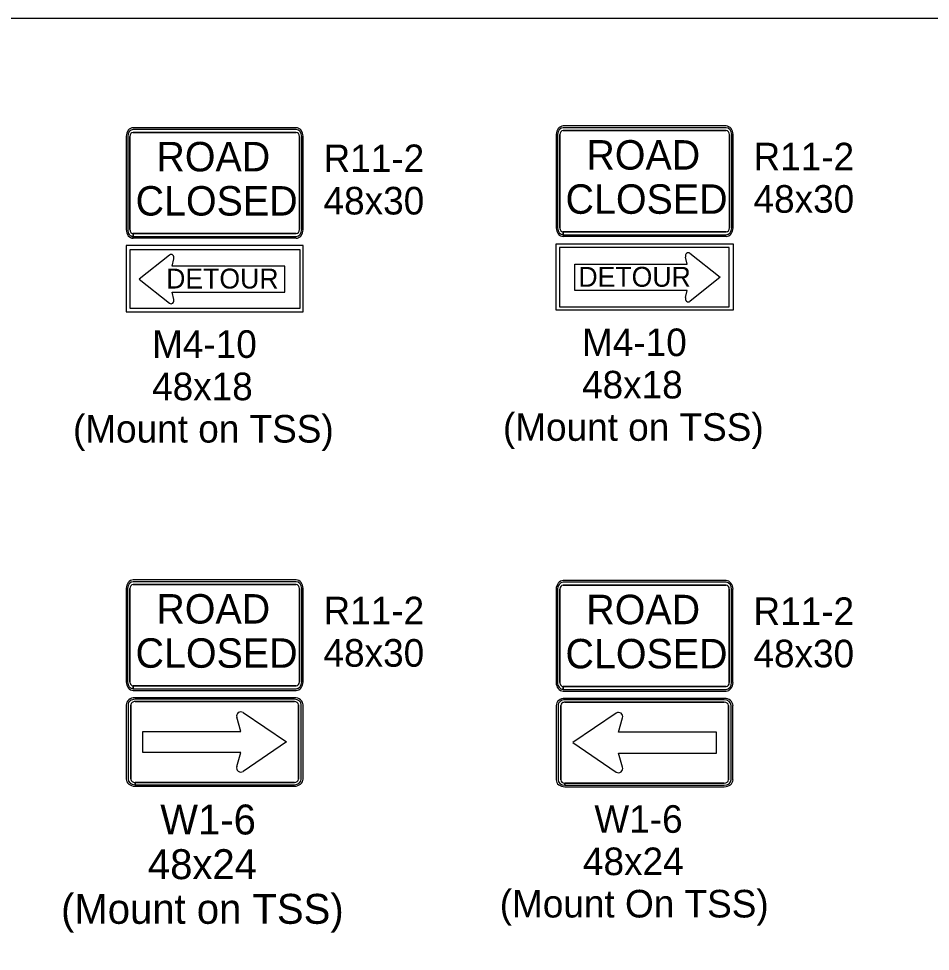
# Model space of a CAD drawing. Extents: x 1458 to 4498, y 17709 to 24109.
# Drawn here: x 3157 to 3652, y 21403 to 21909 of the extents above; entities that cross this region are included whole.
import ezdxf

# ---------------------------------------------------------------- set-up
doc = ezdxf.new("R2010")
doc.units = 0
doc.layers.add('P_TRAF_TCP_General', color=7, linetype='Continuous')

msp = doc.modelspace()

# ---------------------------------------------------------------- linework, layer by layer
at = {"layer": 'P_TRAF_TCP_General'}
for p, q in [((3307.71, 21849.89), (3219.25, 21849.89)), ((3307.71, 21848.95), (3219.25, 21848.95)), ((3307.71, 21848.95), (3219.25, 21848.95)), ((3307.71, 21847.39), (3219.25, 21847.39)), ((3219.25, 21847.39), (3307.71, 21847.39)), ((3541.06, 21850.85), (3452.59, 21850.85)), ((3541.06, 21849.91), (3452.59, 21849.91)), ((3541.06, 21849.91), (3452.59, 21849.91)), ((3541.06, 21848.35), (3452.59, 21848.35)), ((3452.59, 21848.35), (3541.06, 21848.35)), ((3215.5, 21845.2), (3215.5, 21794.6)), ((3216.25, 21845.2), (3216.25, 21794.6)), ((3216.25, 21845.2), (3216.25, 21794.6)), ((3217.5, 21845.2), (3217.5, 21794.6)), ((3217.5, 21794.6), (3217.5, 21845.2)), ((3309.46, 21794.6), (3309.46, 21845.2)), ((3309.46, 21845.2), (3309.46, 21794.6)), ((3310.71, 21794.6), (3310.71, 21845.2)), ((3310.71, 21794.6), (3310.71, 21845.2)), ((3311.46, 21794.6), (3311.46, 21845.2)), ((3448.85, 21846.16), (3448.85, 21795.56)), ((3449.6, 21846.16), (3449.6, 21795.56)), ((3449.6, 21846.16), (3449.6, 21795.56)), ((3450.84, 21846.16), (3450.84, 21795.56)), ((3450.84, 21795.56), (3450.84, 21846.16)), ((3542.81, 21795.56), (3542.81, 21846.16)), ((3542.81, 21846.16), (3542.81, 21795.56)), ((3544.06, 21795.56), (3544.06, 21846.16)), ((3544.06, 21795.56), (3544.06, 21846.16)), ((3544.81, 21795.56), (3544.81, 21846.16)), ((3219.25, 21792.41), (3307.71, 21792.41)), ((3219.25, 21790.85), (3219.25, 21792.41)), ((3307.71, 21792.41), (3219.26, 21792.41)), ((3219.26, 21792.41), (3219.26, 21790.85)), ((3452.59, 21793.37), (3541.06, 21793.37)), ((3452.59, 21791.81), (3452.59, 21793.37)), ((3452.59, 21791.81), (3541.06, 21791.81)), ((3541.06, 21793.37), (3452.61, 21793.37)), ((3452.61, 21793.37), (3452.61, 21791.81)), ((3452.61, 21791.81), (3541.06, 21791.81)), ((3307.71, 21789.91), (3218.91, 21789.91)), ((3219.25, 21790.85), (3307.71, 21790.85)), ((3219.26, 21790.85), (3307.71, 21790.85)), ((3541.06, 21790.87), (3452.25, 21790.87)), ((3521.39, 21781.76), (3537.81, 21768.69)), ((3238.93, 21780.8), (3222.51, 21767.74)), ((3240.37, 21774.81), (3241.34, 21778.73)), ((3519.96, 21775.77), (3518.99, 21779.69)), ((3301.48, 21774.81), (3240.37, 21774.81)), ((3301.48, 21760.67), (3301.48, 21774.81)), ((3458.84, 21775.77), (3519.96, 21775.77)), ((3458.84, 21761.62), (3458.84, 21775.77)), ((3222.51, 21767.74), (3238.92, 21754.68)), ((3537.81, 21768.69), (3521.4, 21755.64)), ((3519.96, 21761.62), (3458.84, 21761.62)), ((3518.98, 21757.68), (3519.96, 21761.62)), ((3241.34, 21756.72), (3240.37, 21760.67)), ((3240.37, 21760.67), (3301.48, 21760.67)), ((3307.69, 21604.36), (3219.23, 21604.36)), ((3215.48, 21599.67), (3215.48, 21549.07)), ((3216.23, 21599.67), (3216.23, 21549.07)), ((3216.23, 21599.67), (3216.23, 21549.07)), ((3217.48, 21599.67), (3217.48, 21549.07)), ((3217.48, 21549.07), (3217.48, 21599.67)), ((3307.69, 21603.42), (3219.23, 21603.42)), ((3307.69, 21603.42), (3219.23, 21603.42)), ((3307.69, 21601.86), (3219.23, 21601.86)), ((3219.23, 21601.86), (3307.69, 21601.86)), ((3309.44, 21549.07), (3309.44, 21599.67)), ((3309.44, 21599.67), (3309.44, 21549.07)), ((3310.69, 21549.07), (3310.69, 21599.67)), ((3310.69, 21549.07), (3310.69, 21599.67)), ((3311.44, 21549.07), (3311.44, 21599.67)), ((3448.8, 21599.33), (3448.8, 21548.72)), ((3449.55, 21599.33), (3449.55, 21548.72)), ((3449.55, 21599.33), (3449.55, 21548.72)), ((3450.8, 21599.33), (3450.8, 21548.72)), ((3450.8, 21548.72), (3450.8, 21599.33)), ((3541.02, 21604.01), (3452.55, 21604.01)), ((3541.02, 21603.08), (3452.55, 21603.08)), ((3541.02, 21603.08), (3452.55, 21603.08)), ((3541.02, 21601.51), (3452.55, 21601.51)), ((3452.55, 21601.51), (3541.02, 21601.51)), ((3542.76, 21548.72), (3542.76, 21599.33)), ((3542.76, 21599.33), (3542.76, 21548.72)), ((3544.01, 21548.72), (3544.01, 21599.33)), ((3544.01, 21548.72), (3544.01, 21599.33)), ((3544.76, 21548.72), (3544.76, 21599.33)), ((3219.23, 21546.88), (3307.69, 21546.88)), ((3219.23, 21545.32), (3219.23, 21546.88)), ((3219.23, 21545.32), (3307.69, 21545.32)), ((3219.23, 21544.38), (3307.69, 21544.38)), ((3307.69, 21546.88), (3219.24, 21546.88)), ((3219.24, 21546.88), (3219.24, 21545.32)), ((3219.24, 21545.32), (3307.69, 21545.32)), ((3452.55, 21546.54), (3541.02, 21546.54)), ((3452.55, 21544.97), (3452.55, 21546.54)), ((3452.55, 21544.97), (3541.02, 21544.97)), ((3452.55, 21544.04), (3541.01, 21544.04)), ((3541.02, 21546.54), (3452.56, 21546.54)), ((3452.56, 21546.54), (3452.56, 21544.97)), ((3452.56, 21544.97), (3541.02, 21544.97)), ((3306.7, 21540.38), (3220.23, 21540.38)), ((3306.7, 21539.58), (3220.23, 21539.58)), ((3540.02, 21540.04), (3453.55, 21540.04)), ((3540.02, 21539.24), (3453.55, 21539.24)), ((3215.48, 21536.59), (3215.48, 21496.2)), ((3216.48, 21536.59), (3216.48, 21496.2)), ((3217.98, 21536.59), (3217.98, 21496.2)), ((3217.98, 21496.2), (3217.98, 21536.59)), ((3306.7, 21538.38), (3220.23, 21538.38)), ((3220.23, 21538.38), (3306.7, 21538.38)), ((3308.94, 21496.2), (3308.94, 21536.59)), ((3308.94, 21536.59), (3308.94, 21496.2)), ((3310.44, 21496.2), (3310.44, 21536.59)), ((3311.44, 21496.2), (3311.44, 21536.59)), ((3448.8, 21536.24), (3448.8, 21495.86)), ((3449.8, 21536.24), (3449.8, 21495.86)), ((3451.3, 21536.24), (3451.3, 21495.86)), ((3451.3, 21495.86), (3451.3, 21536.24)), ((3540.02, 21538.04), (3453.55, 21538.04)), ((3453.55, 21538.04), (3540.02, 21538.04)), ((3542.27, 21495.86), (3542.27, 21536.24)), ((3542.27, 21536.24), (3542.27, 21495.86)), ((3543.77, 21495.86), (3543.77, 21536.24)), ((3544.76, 21495.86), (3544.76, 21536.24)), ((3277.67, 21522.07), (3275.42, 21529.84)), ((3278.89, 21532.36), (3302.46, 21516.39)), ((3481.37, 21532.02), (3457.8, 21516.05)), ((3482.58, 21521.72), (3484.84, 21529.49)), ((3224.48, 21522.07), (3277.67, 21522.07)), ((3224.48, 21510.72), (3224.48, 21522.07)), ((3535.78, 21521.72), (3482.58, 21521.72)), ((3535.78, 21510.38), (3535.78, 21521.72)), ((3302.46, 21516.39), (3278.86, 21500.41)), ((3457.8, 21516.05), (3481.39, 21500.07)), ((3277.67, 21510.72), (3224.48, 21510.72)), ((3275.43, 21503), (3277.67, 21510.72)), ((3484.82, 21502.65), (3482.58, 21510.38)), ((3482.58, 21510.38), (3535.78, 21510.38)), ((3220.23, 21494.4), (3306.7, 21494.4)), ((3220.23, 21493.2), (3220.23, 21494.4)), ((3306.7, 21494.4), (3220.25, 21494.4)), ((3220.25, 21494.4), (3220.25, 21493.2)), ((3220.25, 21493.2), (3306.7, 21493.2)), ((3453.55, 21494.06), (3540.02, 21494.06)), ((3453.55, 21492.86), (3453.55, 21494.06)), ((3540.02, 21494.06), (3453.57, 21494.06)), ((3453.57, 21494.06), (3453.57, 21492.86)), ((3220.23, 21492.4), (3306.7, 21492.4)), ((3453.55, 21492.06), (3540.02, 21492.06)), ((3453.57, 21492.86), (3540.02, 21492.86))]:
    msp.add_line(p, q, dxfattribs=at)
for points in [[(4498.44, 21909.14), (1458.44, 21909.14), (1458.44, 19909.14), (4498.44, 19909.14)], [(3448.85, 21786.87), (3544.81, 21786.87), (3544.81, 21750.89), (3448.85, 21750.89)], [(3311.48, 21785.92), (3215.51, 21785.92), (3215.51, 21749.93), (3311.48, 21749.93)], [(3309.64, 21751.74), (3217.61, 21751.74), (3217.61, 21783.85), (3309.64, 21783.85)], [(3450.68, 21752.69), (3542.71, 21752.69), (3542.71, 21784.8), (3450.68, 21784.8)]]:
    msp.add_lwpolyline(points, close=True, dxfattribs=at)
for centre, start, end in [((3277.61, 21530.47), 55.884, 196.1777), ((3482.65, 21530.13), 343.8223, 124.116), ((3277.61, 21502.31), 162.5706, 303.37), ((3482.65, 21501.97), 236.63, 17.4294)]:
    msp.add_arc(centre, 2.28, start, end, dxfattribs=at)
for centre, major_axis, ratio, start_param, end_param in [((3219.25, 21845.2), (0, 4.69), 0.8, 0, 1.570796), ((3219.25, 21845.2), (0, 3.75), 0.8, 0, 1.570796), ((3219.25, 21845.2), (0, 3.75), 0.8, 0, 1.570796), ((3219.25, 21845.2), (0, 2.19), 0.8, 0, 1.570796), ((3219.25, 21845.2), (0, 2.19), 0.8, 0, 1.570796), ((3307.71, 21845.2), (0, 4.69), 0.8, 4.712389, 6.283185), ((3307.71, 21845.2), (0, 3.75), 0.8, 4.712389, 6.283185), ((3307.71, 21845.2), (0, 3.75), 0.8, 4.712389, 6.283185), ((3307.71, 21845.2), (0, 2.19), 0.8, 4.712389, 6.283185), ((3307.71, 21845.2), (0, 2.19), 0.8, 4.712389, 6.283185), ((3452.59, 21846.16), (0, 4.69), 0.8, 0, 1.570796), ((3452.59, 21846.16), (0, 3.75), 0.8, 0, 1.570796), ((3452.59, 21846.16), (0, 3.75), 0.8, 0, 1.570796), ((3452.59, 21846.16), (0, 2.19), 0.8, 0, 1.570796), ((3452.59, 21846.16), (0, 2.19), 0.8, 0, 1.570796), ((3541.06, 21846.16), (0, 4.69), 0.8, 4.712389, 6.283185), ((3541.06, 21846.16), (0, 3.75), 0.8, 4.712389, 6.283185), ((3541.06, 21846.16), (0, 3.75), 0.8, 4.712389, 6.283185), ((3541.06, 21846.16), (0, 2.19), 0.8, 4.712389, 6.283185), ((3541.06, 21846.16), (0, 2.19), 0.8, 4.712389, 6.283185), ((3219.25, 21794.6), (0, 4.69), 0.8, 1.570796, 3.141593), ((3219.25, 21794.6), (0, 3.75), 0.8, 1.570796, 3.141593), ((3219.25, 21794.6), (0, 3.75), 0.8, 1.570796, 3.141593), ((3219.25, 21794.6), (0, 2.19), 0.8, 1.570796, 3.141593), ((3219.25, 21794.6), (0, 2.19), 0.8, 1.570796, 3.141593), ((3307.71, 21794.6), (0, 3.75), 0.8, 3.141593, 4.712389), ((3307.71, 21794.6), (0, 2.19), 0.8, 3.141593, 4.712389), ((3307.71, 21794.6), (0, 3.75), 0.8, 3.141593, 4.712389), ((3307.71, 21794.6), (0, 2.19), 0.8, 3.141593, 4.712389), ((3307.71, 21794.6), (0, 4.69), 0.8, 3.141593, 4.712389), ((3452.59, 21795.56), (0, 4.69), 0.8, 1.570796, 3.141593), ((3452.59, 21795.56), (0, 3.75), 0.8, 1.570796, 3.141593), ((3452.59, 21795.56), (0, 3.75), 0.8, 1.570796, 3.141593), ((3452.59, 21795.56), (0, 2.19), 0.8, 1.570796, 3.141593), ((3452.59, 21795.56), (0, 2.19), 0.8, 1.570796, 3.141593), ((3541.06, 21795.56), (0, 3.75), 0.8, 3.141593, 4.712389), ((3541.06, 21795.56), (0, 2.19), 0.8, 3.141593, 4.712389), ((3541.06, 21795.56), (0, 3.75), 0.8, 3.141593, 4.712389), ((3541.06, 21795.56), (0, 2.19), 0.8, 3.141593, 4.712389), ((3541.06, 21795.56), (0, 4.69), 0.8, 3.141593, 4.712389), ((3520.51, 21780.21), (0, 1.86), 0.851337, 5.694845, 8.136509), ((3239.81, 21779.25), (0, 1.86), 0.851337, 4.429862, 6.871525), ((3239.81, 21756.22), (0, -1.86), 0.851337, 5.687791, 8.124104), ((3520.51, 21757.18), (0, -1.86), 0.851337, 4.442267, 6.878579), ((3219.23, 21599.67), (0, 4.69), 0.8, 0, 1.570796), ((3307.69, 21599.67), (0, 4.69), 0.8, 4.712389, 6.283185), ((3219.23, 21599.67), (0, 3.75), 0.8, 0, 1.570796), ((3219.23, 21599.67), (0, 3.75), 0.8, 0, 1.570796), ((3219.23, 21599.67), (0, 2.19), 0.8, 0, 1.570796), ((3219.23, 21599.67), (0, 2.19), 0.8, 0, 1.570796), ((3307.69, 21599.67), (0, 3.75), 0.8, 4.712389, 6.283185), ((3307.69, 21599.67), (0, 3.75), 0.8, 4.712389, 6.283185), ((3307.69, 21599.67), (0, 2.19), 0.8, 4.712389, 6.283185), ((3307.69, 21599.67), (0, 2.19), 0.8, 4.712389, 6.283185), ((3452.55, 21599.33), (0, 4.69), 0.8, 0, 1.570796), ((3452.55, 21599.33), (0, 3.75), 0.8, 0, 1.570796), ((3452.55, 21599.33), (0, 3.75), 0.8, 0, 1.570796), ((3452.55, 21599.33), (0, 2.19), 0.8, 0, 1.570796), ((3452.55, 21599.33), (0, 2.19), 0.8, 0, 1.570796), ((3541.02, 21599.33), (0, 4.69), 0.8, 4.712389, 6.283185), ((3541.02, 21599.33), (0, 3.75), 0.8, 4.712389, 6.283185), ((3541.02, 21599.33), (0, 3.75), 0.8, 4.712389, 6.283185), ((3541.02, 21599.33), (0, 2.19), 0.8, 4.712389, 6.283185), ((3541.02, 21599.33), (0, 2.19), 0.8, 4.712389, 6.283185), ((3219.23, 21549.07), (0, 4.69), 0.8, 1.570796, 3.141593), ((3219.23, 21549.07), (0, 3.75), 0.8, 1.570796, 3.141593), ((3219.23, 21549.07), (0, 3.75), 0.8, 1.570796, 3.141593), ((3219.23, 21549.07), (0, 2.19), 0.8, 1.570796, 3.141593), ((3219.23, 21549.07), (0, 2.19), 0.8, 1.570796, 3.141593), ((3307.69, 21549.07), (0, 3.75), 0.8, 3.141593, 4.712389), ((3307.69, 21549.07), (0, 2.19), 0.8, 3.141593, 4.712389), ((3307.69, 21549.07), (0, 3.75), 0.8, 3.141593, 4.712389), ((3307.69, 21549.07), (0, 2.19), 0.8, 3.141593, 4.712389), ((3307.69, 21549.07), (0, 4.69), 0.8, 3.141593, 4.712389), ((3452.55, 21548.72), (0, 4.69), 0.8, 1.570796, 3.141593), ((3452.55, 21548.72), (0, 3.75), 0.8, 1.570796, 3.141593), ((3452.55, 21548.72), (0, 3.75), 0.8, 1.570796, 3.141593), ((3452.55, 21548.72), (0, 2.19), 0.8, 1.570796, 3.141593), ((3452.55, 21548.72), (0, 2.19), 0.8, 1.570796, 3.141593), ((3541.02, 21548.72), (0, 3.75), 0.8, 3.141593, 4.712389), ((3541.02, 21548.72), (0, 2.19), 0.8, 3.141593, 4.712389), ((3541.02, 21548.72), (0, 3.75), 0.8, 3.141593, 4.712389), ((3541.02, 21548.72), (0, 2.19), 0.8, 3.141593, 4.712389), ((3541.02, 21548.72), (0, 4.69), 0.8, 3.141593, 4.712389), ((3220.23, 21536.59), (4.75, 0), 0.8, 1.570796, 3.141593), ((3220.23, 21536.59), (3.75, 0), 0.8, 1.570796, 3.141593), ((3306.7, 21536.59), (4.75, 0), 0.8, 0, 1.570796), ((3306.7, 21536.59), (3.75, 0), 0.8, 0, 1.570796), ((3453.55, 21536.24), (4.75, 0), 0.8, 1.570796, 3.141593), ((3453.55, 21536.24), (3.75, 0), 0.8, 1.570796, 3.141593), ((3540.02, 21536.24), (4.75, 0), 0.8, 0, 1.570796), ((3540.02, 21536.24), (3.75, 0), 0.8, 0, 1.570796), ((3220.23, 21536.59), (2.25, 0), 0.8, 1.570796, 3.141593), ((3220.23, 21536.59), (2.25, 0), 0.8, 1.570796, 3.141593), ((3306.7, 21536.59), (2.25, 0), 0.8, 0, 1.570796), ((3306.7, 21536.59), (2.25, 0), 0.8, 0, 1.570796), ((3453.55, 21536.24), (2.25, 0), 0.8, 1.570796, 3.141593), ((3453.55, 21536.24), (2.25, 0), 0.8, 1.570796, 3.141593), ((3540.02, 21536.24), (2.25, 0), 0.8, 0, 1.570796), ((3540.02, 21536.24), (2.25, 0), 0.8, 0, 1.570796), ((3220.23, 21496.2), (4.75, 0), 0.8, 3.141593, 4.712389), ((3220.23, 21496.2), (3.75, 0), 0.8, 3.141593, 4.712389), ((3220.23, 21496.2), (2.25, 0), 0.8, 3.141593, 4.712389), ((3220.23, 21496.2), (2.25, 0), 0.8, 3.141593, 4.712389), ((3306.7, 21496.2), (2.25, 0), 0.8, 4.712389, 6.283185), ((3306.7, 21496.2), (3.75, 0), 0.8, 4.712389, 6.283185), ((3306.7, 21496.2), (2.25, 0), 0.8, 4.712389, 6.283185), ((3306.7, 21496.2), (4.75, 0), 0.8, 4.712389, 6.283185), ((3453.55, 21495.86), (4.75, 0), 0.8, 3.141593, 4.712389), ((3453.55, 21495.86), (3.75, 0), 0.8, 3.141593, 4.712389), ((3453.55, 21495.86), (2.25, 0), 0.8, 3.141593, 4.712389), ((3453.55, 21495.86), (2.25, 0), 0.8, 3.141593, 4.712389), ((3540.02, 21495.86), (2.25, 0), 0.8, 4.712389, 6.283185), ((3540.02, 21495.86), (3.75, 0), 0.8, 4.712389, 6.283185), ((3540.02, 21495.86), (2.25, 0), 0.8, 4.712389, 6.283185), ((3540.02, 21495.86), (4.75, 0), 0.8, 4.712389, 6.283185)]:
    msp.add_ellipse(centre, major_axis=major_axis, ratio=ratio, start_param=start_param, end_param=end_param, dxfattribs=at)

# ---------------------------------------------------------------- texts
for s, height, p in [('ROAD', 15.994, (3231.83, 21826.21)), ('ROAD', 15.994, (3465.18, 21827.17)), ('R11-2', 14.994, (3322.56, 21825.79)), ('R11-2', 14.994, (3555.9, 21826.74)), ('CLOSED', 15.994, (3220.55, 21802.22)), ('48x30', 14.994, (3322.56, 21802.8)), ('CLOSED', 15.994, (3453.89, 21803.18)), ('48x30', 14.994, (3555.9, 21803.75)), ('DETOUR', 10.8, (3460.88, 21763.57)), ('M4-10', 14.994, (3462.85, 21725.9)), ('M4-10', 14.994, (3229.51, 21724.94)), ('48x18', 14.994, (3229.51, 21701.95)), ('48x18', 14.994, (3462.85, 21702.91)), ('(Mount on TSS)', 14.994, (3419.91, 21679.91)), ('(Mount on TSS)', 14.994, (3186.57, 21678.96)), ('ROAD', 15.994, (3231.81, 21580.68)), ('R11-2', 14.994, (3322.54, 21580.25)), ('ROAD', 15.994, (3465.13, 21580.34)), ('R11-2', 14.994, (3555.86, 21579.91)), ('CLOSED', 15.994, (3220.53, 21556.69)), ('48x30', 14.994, (3322.54, 21557.26)), ('CLOSED', 15.994, (3453.85, 21556.35)), ('48x30', 14.994, (3555.86, 21556.92)), ('W1-6', 16.25, (3233.92, 21466.16)), ('W1-6', 14.994, (3469.53, 21467.07)), ('48x24', 16.25, (3227.22, 21441.91)), ('48x24', 14.994, (3463.34, 21444.08)), ('(Mount on TSS)', 16.2505, (3180.1, 21417.66)), ('(Mount On TSS)', 14.994, (3418.18, 21421.09))]:
    msp.add_text(s, height=height, dxfattribs=at).set_placement(p)
msp.add_text('DETOUR', height=10.8, rotation=360, dxfattribs=at).set_placement((3237.15, 21762.61))

doc.saveas('drawing.dxf')
